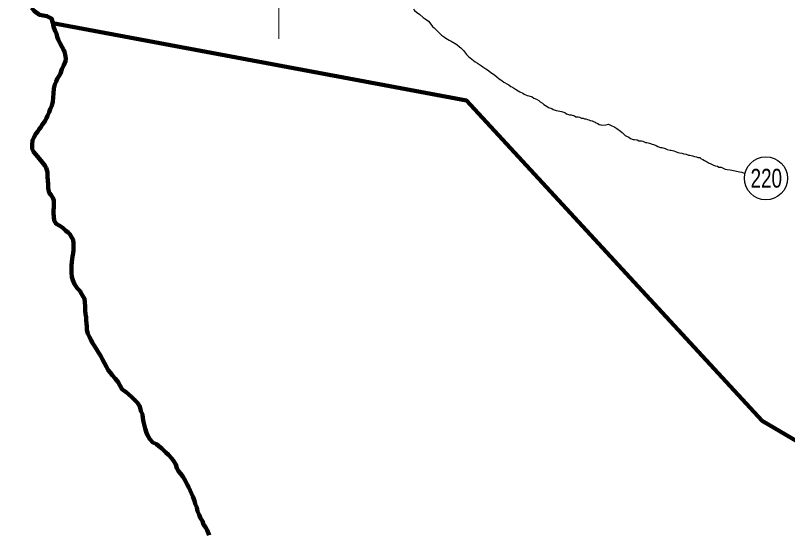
# Model space of a CAD drawing. Extents: x 553962 to 842807, y 8883888 to 9032388.
# Drawn here: x 645098 to 659476, y 8939787 to 8949437 of the extents above; entities that cross this region are included whole.
import ezdxf
from ezdxf.enums import TextEntityAlignment as Align

# ---------------------------------------------------------------- set-up
doc = ezdxf.new("R2010")
doc.units = 0
doc.header["$LTSCALE"] = 150
for name, color, linetype, lineweight in [('12', 7, 'Continuous', 25), ('2', 7, 'Continuous', 13), ('24', 7, 'Continuous', 25), ('48', 7, 'Continuous', 25), ('9', 7, 'Continuous', 90)]:
    doc.layers.add(name, color=color, linetype=linetype, lineweight=lineweight)

msp = doc.modelspace()

# ---------------------------------------------------------------- linework, layer by layer
at = {"layer": '12'}
for points in [[(652507.9, 8949552.8), (652526.9, 8949530.3), (652569.2, 8949497.5), (652626.3, 8949452.1), (652693.5, 8949399.1), (652728.3, 8949373.8), (652790.5, 8949328.3), (652815.3, 8949300.6), (652867.3, 8949232.7), (652894.6, 8949204.9), (652949.2, 8949149.5), (652979, 8949124.3), (653033.6, 8949071.3), (653085.8, 8949030.9), (653110.7, 8949013.2), (653173, 8948977.8), (653212.8, 8948957.5), (653287.6, 8948916.9), (653314.9, 8948894.2), (653367.1, 8948853.8), (653392, 8948833.6), (653441.6, 8948785.7)], [(653441.6, 8948785.7), (653498.6, 8948710.3), (653535.8, 8948672.5), (653595.5, 8948622), (653660.1, 8948571.5), (653702.4, 8948546.2), (653779.6, 8948498.1), (653804.4, 8948477.9), (653859.2, 8948442.5), (653889.1, 8948422.3), (653946.3, 8948381.8), (653971.1, 8948361.6), (654018.4, 8948328.8), (654070.6, 8948288.4), (654100.4, 8948263.2), (654160.1, 8948220.2), (654195, 8948194.9), (654262.2, 8948156.9), (654284.6, 8948141.8), (654324.4, 8948114), (654351.8, 8948098.8), (654409.1, 8948063.3), (654458.8, 8948030.5), (654488.7, 8948015.2), (654548.5, 8947987.3), (654573.4, 8947972.1), (654628.3, 8947946.7), (654655.7, 8947941.5), (654718.1, 8947918.6), (654752.9, 8947893.3), (654800.3, 8947875.5), (654842.6, 8947850.2), (654867.5, 8947825), (654909.8, 8947804.7), (654937.1, 8947779.4), (654999.3, 8947739), (655026.8, 8947723.8), (655084.1, 8947705.9), (655111.5, 8947685.7), (655168.9, 8947665.2), (655203.9, 8947662.5), (655268.8, 8947647.1), (655328.6, 8947626.6), (655358.5, 8947606.4), (655415.9, 8947588.5), (655445.9, 8947588.3), (655505.8, 8947565.4), (655533.2, 8947550.2), (655578.2, 8947547.4), (655600.6, 8947539.7), (655640.5, 8947524.4), (655668, 8947521.8), (655698, 8947514), (655720.4, 8947511.4), (655747.8, 8947496.2), (655772.8, 8947493.5), (655802.8, 8947483.3), (655835.2, 8947473.1), (655860.1, 8947462.9), (655892.6, 8947450.2), (655915, 8947435), (655942.4, 8947424.8), (655969.7, 8947404.6), (655997.2, 8947401.9), (656019.7, 8947391.7), (656089.8, 8947398.8)], [(656089.8, 8947398.8), (656144.9, 8947413.4), (656177.2, 8947393.2), (656259.5, 8947355.1), (656294.3, 8947332.3), (656364, 8947281.8), (656393.8, 8947254.1), (656450.9, 8947201.1), (656475.8, 8947185.9), (656523.2, 8947168.1), (656553, 8947145.4), (656602.9, 8947127.5), (656627.9, 8947127.3), (656675.4, 8947119.5), (656705.3, 8947104.3), (656757.8, 8947101.5), (656780.2, 8947093.8), (656830.1, 8947073.4), (656857.6, 8947070.8), (656907.5, 8947055.4), (656952.4, 8947040.1), (656977.4, 8947034.9), (657032.2, 8947012), (657059.6, 8946996.8), (657112, 8946978.9), (657137, 8946978.8), (657199.4, 8946960.8), (657234.3, 8946943.1), (657289.2, 8946927.7), (657311.7, 8946927.6), (657356.6, 8946912.2), (657391.6, 8946904.5), (657431.4, 8946884.2), (657466.4, 8946879), (657506.4, 8946871.2), (657546.3, 8946858.4), (657586.2, 8946850.6), (657631.1, 8946835.3), (657656.1, 8946832.6), (657708.6, 8946824.8), (657741, 8946807.1), (657781, 8946801.8), (657808.4, 8946794.1), (657840.9, 8946788.9), (657868.2, 8946768.7), (657898.1, 8946753.4), (657930.5, 8946735.7), (657965.4, 8946717.9), (658005.2, 8946692.6), (658045.1, 8946672.3), (658085, 8946652.1), (658129.8, 8946634.2), (658172.3, 8946628.9), (658194.7, 8946611.3), (658242.2, 8946608.4), (658277.1, 8946590.7), (658314.5, 8946572.9), (658354.4, 8946567.7), (658406.9, 8946559.8), (658439.3, 8946552.1), (658501.8, 8946544.2), (658524.3, 8946536.5), (658556.7, 8946531.3), (658581.7, 8946523.6), (658624.1, 8946515.8), (658678.1, 8946495.9)]]:
    msp.add_lwpolyline(points, dxfattribs=at)
at = {"layer": '2'}
msp.add_line((650000, 8949000), (650000, 8951000), dxfattribs=at)
at = {"layer": '24', "lineweight": 53}
for points in [[(645398.8, 8949579.9), (645451.4, 8949513.8), (645546.2, 8949449.6), (645683.8, 8949425.1), (645771.3, 8949377.1), (645790.9, 8949299.5), (645808.1, 8949229.4), (645840.2, 8949144.1), (645862.5, 8949099), (645877.2, 8949041.4), (645894.5, 8948988.8), (645929.2, 8948913.5), (645968.9, 8948848.3), (645990.2, 8948804.6)], [(645990.2, 8948804.6), (646010.9, 8948758.1), (646021.2, 8948711.7), (646036.8, 8948634.2), (646031.6, 8948582.6), (646000.6, 8948510.3), (645964.4, 8948438), (645936.5, 8948358.1), (645911.3, 8948313.2), (645873.5, 8948253.4), (645853.2, 8948208.5), (645832.9, 8948151), (645815.1, 8948076.1), (645807.1, 8947983.6), (645799.2, 8947908.6), (645796.4, 8947834.9)], [(645796.4, 8947834.9), (645776, 8947756.1), (645745.7, 8947693.7), (645725.4, 8947636.3), (645695.1, 8947568.9), (645674.8, 8947521.4), (645649.6, 8947474), (645596.7, 8947399.3), (645571.5, 8947356.9), (645541.2, 8947317), (645511, 8947272.1), (645475.8, 8947229.8), (645437.9, 8947162.4), (645412.7, 8947110), (645409.8, 8947032.5), (645409.4, 8946954.9), (645431.6, 8946894.8), (645476.4, 8946847), (645541.1, 8946774.1), (645593.3, 8946706.3), (645643.1, 8946643.5), (645668.8, 8946601.4)], [(645668.8, 8946601.4), (645692.5, 8946518.2), (645694.6, 8946428.1), (645699.3, 8946363), (645706.4, 8946292.9), (645706.1, 8946220.4), (645728.2, 8946132.7), (645765.5, 8946092.5), (645792.8, 8946037.3), (645812.6, 8945992.2), (645814.8, 8945939.6), (645812, 8945874.6), (645809.1, 8945802.1), (645808.9, 8945752), (645813.6, 8945684.5), (645820.8, 8945616.9), (645855.5, 8945556.7), (645925.1, 8945520.2)], [(645925.1, 8945520.2), (645980.3, 8945480.9), (646030.3, 8945430.9), (646080.3, 8945396.3), (646111.1, 8945361.7), (646137.1, 8945322.6), (646171.8, 8945257.3), (646176.4, 8945189.8), (646181.1, 8945124.7), (646180.8, 8945062.1), (646173.1, 8945007.1), (646162.8, 8944947.2), (646155, 8944897.2), (646149.8, 8944847.1), (646141.9, 8944777.1), (646139.2, 8944722.1), (646138.8, 8944644.6), (646145.9, 8944567), (646168.2, 8944506.8), (646200.3, 8944434.1), (646247.5, 8944358.8), (646299.8, 8944301), (646309, 8944284.7)], [(646309, 8944284.7), (646346.9, 8944218.2), (646384.2, 8944160.4), (646391.3, 8944097.8), (646395.9, 8944012.8), (646398.1, 8943942.7), (646405.3, 8943872.6), (646412.5, 8943820), (646414.7, 8943755), (646419.5, 8943702.4), (646424.2, 8943637.3), (646428.9, 8943577.3), (646446.1, 8943512.1), (646475.8, 8943444.4), (646508, 8943389.2), (646527.8, 8943344.1), (646562.6, 8943288.9), (646604.8, 8943221.1), (646647, 8943160.8), (646684.3, 8943105.6), (646721.5, 8943027.8), (646756.1, 8942957.6), (646790.8, 8942889.9), (646825.6, 8942829.7), (646865.4, 8942779.4), (646902.7, 8942731.7), (646957.4, 8942676.4), (647012.1, 8942606), (647046.8, 8942538.3), (647076.6, 8942480.6), (647102.9, 8942459), (647151.9, 8942424.7), (647151.9, 8942424.7), (647259.8, 8942331.6), (647323.5, 8942272.8), (647367.7, 8942218.9), (647416.7, 8942155.2), (647431.4, 8942071.9), (647460.8, 8942003.3), (647470.7, 8941934.7), (647485.4, 8941866.1), (647498.6, 8941792.9), (647513.3, 8941742.8), (647538, 8941665.1), (647557.8, 8941619.9), (647597.5, 8941547.2), (647657.2, 8941484.3), (647722.1, 8941454), (647762, 8941421.2), (647826.8, 8941368.3), (647896.5, 8941297.9), (647948.8, 8941250.1), (648011, 8941182.2), (648043.4, 8941142.1), (648083.1, 8941071.8), (648100.2, 8941001.6), (648132.5, 8940948.9), (648170.9, 8940907.9), (648214.2, 8940849.2), (648257.5, 8940775), (648294.6, 8940700.8), (648325.5, 8940642.1), (648353.4, 8940586.5), (648378.1, 8940533.9), (648399.8, 8940478.3), (648430.7, 8940394.8), (648446.2, 8940342.3), (648474, 8940274.3), (648489.2, 8940201.5), (648521.4, 8940133.8), (648546.1, 8940073.6), (648581.1, 8940014.6), (648600.6, 8939953.5), (648636.7, 8939906.2), (648667.3, 8939850.6), (648703.5, 8939758.8)]]:
    msp.add_lwpolyline(points, dxfattribs=at)
at = {"layer": '48'}
msp.add_circle((659073.8, 8946403.8), 401.3, dxfattribs=at)
at = {"layer": '9'}
for points in [[(645398.8, 8949579.9), (645451.4, 8949513.8), (645546.2, 8949449.6), (645683.8, 8949425.1), (645771.3, 8949377.1), (645790.9, 8949299.5), (645808.1, 8949229.4), (645840.2, 8949144.1), (645862.5, 8949099), (645877.2, 8949041.4), (645894.5, 8948988.8), (645929.2, 8948913.5), (645968.9, 8948848.3), (645990.2, 8948804.6)], [(645793.1, 8949290.9), (653495.4, 8947850), (659002.1, 8941889), (662654, 8939737.7), (668185.2, 8933928.8)], [(645990.2, 8948804.6), (646010.9, 8948758.1), (646021.2, 8948711.7), (646036.8, 8948634.2), (646031.6, 8948582.6), (646000.6, 8948510.3), (645964.4, 8948438), (645936.5, 8948358.1), (645911.3, 8948313.2), (645873.5, 8948253.4), (645853.2, 8948208.5), (645832.9, 8948151), (645815.1, 8948076.1), (645807.1, 8947983.6), (645799.2, 8947908.6), (645796.4, 8947834.9)], [(645796.4, 8947834.9), (645776, 8947756.1), (645745.7, 8947693.7), (645725.4, 8947636.3), (645695.1, 8947568.9), (645674.8, 8947521.4), (645649.6, 8947474), (645596.7, 8947399.3), (645571.5, 8947356.9), (645541.2, 8947317), (645511, 8947272.1), (645475.8, 8947229.8), (645437.9, 8947162.4), (645412.7, 8947110), (645409.8, 8947032.5), (645409.4, 8946954.9), (645431.6, 8946894.8), (645476.4, 8946847), (645541.1, 8946774.1), (645593.3, 8946706.3), (645643.1, 8946643.5), (645668.8, 8946601.4)], [(645668.8, 8946601.4), (645692.5, 8946518.2), (645694.6, 8946428.1), (645699.3, 8946363), (645706.4, 8946292.9), (645706.1, 8946220.4), (645728.2, 8946132.7), (645765.5, 8946092.5), (645792.8, 8946037.3), (645812.6, 8945992.2), (645814.8, 8945939.6), (645812, 8945874.6), (645809.1, 8945802.1), (645808.9, 8945752), (645813.6, 8945684.5), (645820.8, 8945616.9), (645855.5, 8945556.7), (645925.1, 8945520.2)], [(645925.1, 8945520.2), (645980.3, 8945480.9), (646030.3, 8945430.9), (646080.3, 8945396.3), (646111.1, 8945361.7), (646137.1, 8945322.6), (646171.8, 8945257.3), (646176.4, 8945189.8), (646181.1, 8945124.7), (646180.8, 8945062.1), (646173.1, 8945007.1), (646162.8, 8944947.2), (646155, 8944897.2), (646149.8, 8944847.1), (646141.9, 8944777.1), (646139.2, 8944722.1), (646138.8, 8944644.6), (646145.9, 8944567), (646168.2, 8944506.8), (646200.3, 8944434.1), (646247.5, 8944358.8), (646299.8, 8944301), (646309, 8944284.7)], [(646309, 8944284.7), (646346.9, 8944218.2), (646384.2, 8944160.4), (646391.3, 8944097.8), (646395.9, 8944012.8), (646398.1, 8943942.7), (646405.3, 8943872.6), (646412.5, 8943820), (646414.7, 8943755), (646419.5, 8943702.4), (646424.2, 8943637.3), (646428.9, 8943577.3), (646446.1, 8943512.1), (646475.8, 8943444.4), (646508, 8943389.2), (646527.8, 8943344.1), (646562.6, 8943288.9), (646604.8, 8943221.1), (646647, 8943160.8), (646684.3, 8943105.6), (646721.5, 8943027.8), (646756.1, 8942957.6), (646790.8, 8942889.9), (646825.6, 8942829.7), (646865.4, 8942779.4), (646902.7, 8942731.7), (646957.4, 8942676.4), (647012.1, 8942606), (647046.8, 8942538.3), (647076.6, 8942480.6), (647102.9, 8942459), (647151.9, 8942424.7), (647151.9, 8942424.7), (647259.8, 8942331.6), (647323.5, 8942272.8), (647367.7, 8942218.9), (647416.7, 8942155.2), (647431.4, 8942071.9), (647460.8, 8942003.3), (647470.7, 8941934.7), (647485.4, 8941866.1), (647498.6, 8941792.9), (647513.3, 8941742.8), (647538, 8941665.1), (647557.8, 8941619.9), (647597.5, 8941547.2), (647657.2, 8941484.3), (647722.1, 8941454), (647762, 8941421.2), (647826.8, 8941368.3), (647896.5, 8941297.9), (647948.8, 8941250.1), (648011, 8941182.2), (648043.4, 8941142.1), (648083.1, 8941071.8), (648100.2, 8941001.6), (648132.5, 8940948.9), (648170.9, 8940907.9), (648214.2, 8940849.2), (648257.5, 8940775), (648294.6, 8940700.8), (648325.5, 8940642.1), (648353.4, 8940586.5), (648378.1, 8940533.9), (648399.8, 8940478.3), (648430.7, 8940394.8), (648446.2, 8940342.3), (648474, 8940274.3), (648489.2, 8940201.5), (648521.4, 8940133.8), (648546.1, 8940073.6), (648581.1, 8940014.6), (648600.6, 8939953.5), (648636.7, 8939906.2), (648667.3, 8939850.6), (648703.5, 8939758.8)]]:
    msp.add_lwpolyline(points, dxfattribs=at)
msp.add_spline([(637260.6, 8972975.8), (641524.5, 8971056.2), (652526.1, 8965412.7), (653164.3, 8965062.8), (670790.5, 8953770.1), (686194, 8943929.9), (696283.3, 8937647.1)], degree=3, dxfattribs=at)

# ---------------------------------------------------------------- texts
at = {"layer": '48', "width": 0.75}
msp.add_text('220', height=350, dxfattribs=at).set_placement((659080.5, 8946230.4), align=Align.CENTER)

doc.saveas('drawing.dxf')
